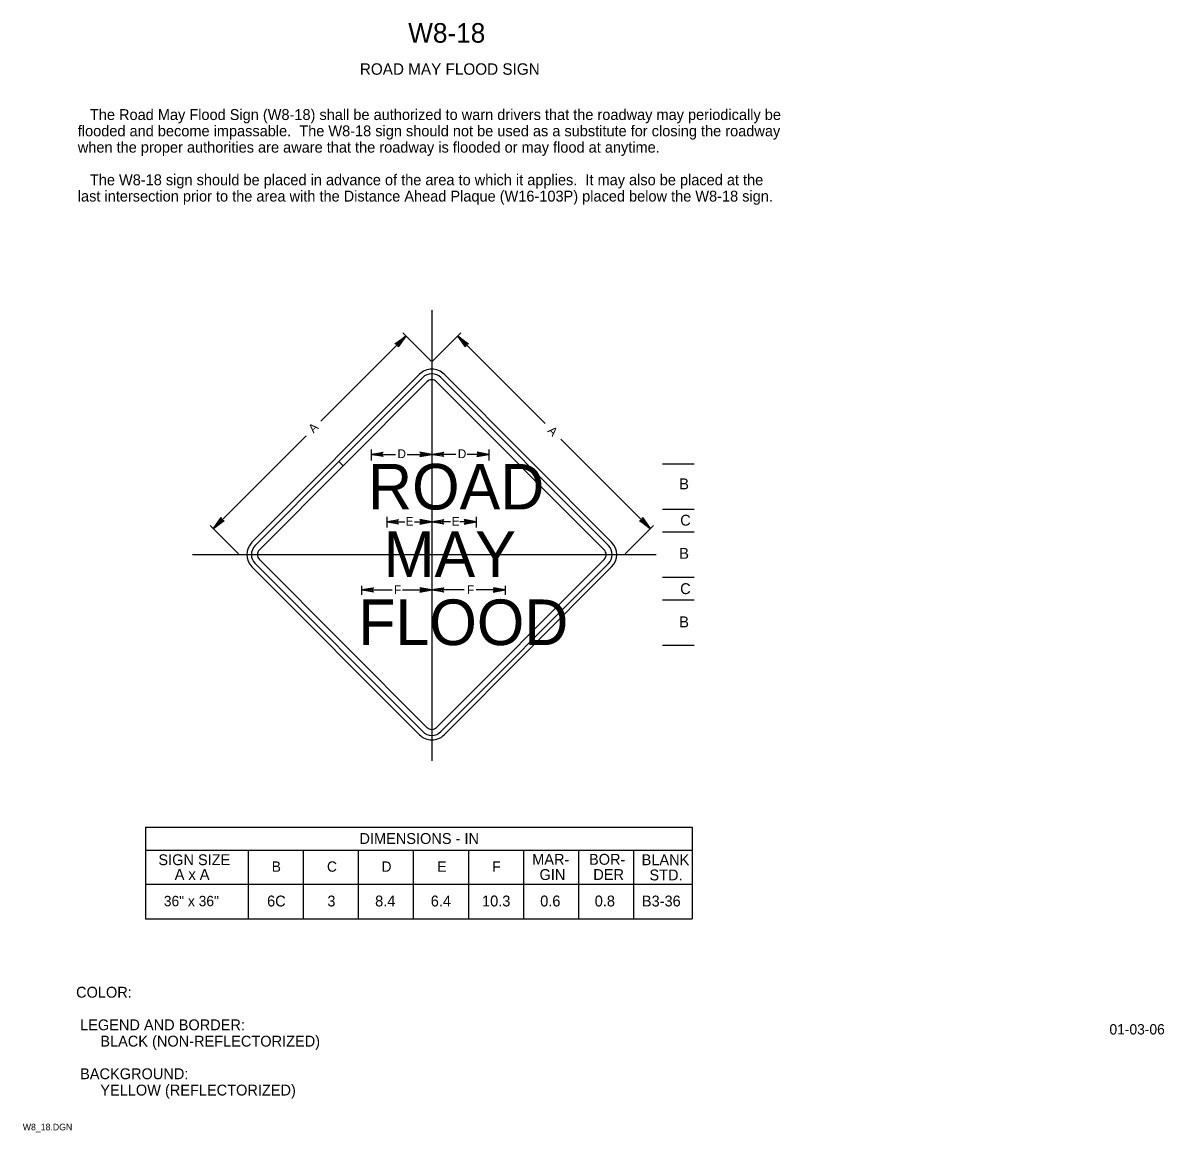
# Model space of a CAD drawing. Extents: x 0.013 to 0.275, y 0.004 to 0.259.
import ezdxf

# ---------------------------------------------------------------- set-up
doc = ezdxf.new("R2010")
doc.units = 0
for name, color, linetype in [('1', 7, 'Continuous'), ('2', 7, 'Continuous'), ('3', 7, 'Continuous'), ('4', 7, 'Continuous')]:
    doc.layers.add(name, color=color, linetype=linetype)

# ---------------------------------------------------------------- blocks, each defined once
blk = doc.blocks.new('RARROW')
at = {"layer": '3'}
for p, q in [((-2.156, 0.28500000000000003), (-2.2665, 0.384625)), ((-2.2665, 0.384625), (0, 0)), ((0, 0), (-2.2665, -0.379125)), ((-2.156, 0.28500000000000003), (-2.075625, 0.12075)), ((0, 0), (-2.156, 0.28500000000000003)), ((-2.14975, -0.2705), (0, 0)), ((-2.075625, 0.12075), (0, 0)), ((0, 0), (-2.074, -0.108)), ((-2.2665, -0.379125), (-2.14975, -0.2705)), ((-2.074, -0.108), (-2.14975, -0.2705))]:
    blk.add_line(p, q, dxfattribs=at)

msp = doc.modelspace()

# ---------------------------------------------------------------- linework, layer by layer
at = {"layer": '2'}
for p, q in [((0.08529993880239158, 0.15817754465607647), (0.10455482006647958, 0.1774918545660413)), ((0.10553914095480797, 0.17651056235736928), (0.08628425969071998, 0.15719625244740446)), ((0.14626937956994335, 0.13788194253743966), (0.10775961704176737, 0.17651056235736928)), ((0.1087439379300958, 0.17749185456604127), (0.14725370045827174, 0.13886323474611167)), ((0.06604505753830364, 0.13886323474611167), (0.08529993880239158, 0.15817754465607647)), ((0.08529993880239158, 0.15817754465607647), (0.08628425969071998, 0.15719625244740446)), ((0.08628425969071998, 0.15719625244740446), (0.08529993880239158, 0.15817754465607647)), ((0.08628425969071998, 0.15719625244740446), (0.06702937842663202, 0.13788194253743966)), ((0.10455482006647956, 0.09605838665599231), (0.06604505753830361, 0.13468700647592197)), ((0.06702937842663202, 0.13566829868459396), (0.10553914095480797, 0.0970396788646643)), ((0.10775961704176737, 0.0970396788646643), (0.14626937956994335, 0.13566829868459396)), ((0.14725370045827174, 0.13468700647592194), (0.10874393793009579, 0.09605838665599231))]:
    msp.add_line(p, q, dxfattribs=at)
for centre, radius, start, end in [((0.10664937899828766, 0.17540374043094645), 0.004, 44.91171689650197, 135.0882831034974), ((0.10664937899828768, 0.17540374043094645), 0.0029576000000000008, 44.9117168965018, 135.08828310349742), ((0.10664937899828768, 0.17540374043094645), 0.0015676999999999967, 44.91171689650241, 135.08828310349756), ((0.0681396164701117, 0.1367751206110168), 0.004, 135.0882831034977, 224.9117168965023), ((0.14515914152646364, 0.1367751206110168), 0.004, 315.08828310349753, 44.9117168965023), ((0.06813961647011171, 0.1367751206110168), 0.002957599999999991, 135.08828310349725, 224.911716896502), ((0.06813961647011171, 0.1367751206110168), 0.0015676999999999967, 135.0882831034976, 224.91171689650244), ((0.14515914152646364, 0.1367751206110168), 0.001567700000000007, 315.08828310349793, 44.91171689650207), ((0.14515914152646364, 0.1367751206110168), 0.0029576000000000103, 315.0882831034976, 44.911716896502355), ((0.10664937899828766, 0.09814650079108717), 0.004, 224.9117168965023, 315.0882831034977), ((0.10664937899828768, 0.09814650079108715), 0.0029576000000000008, 224.91171689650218, 315.0882831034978), ((0.10664937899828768, 0.09814650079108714), 0.0015676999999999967, 224.91171689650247, 315.0882831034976)]:
    msp.add_arc(centre, radius, start, end, dxfattribs=at)
at = {"layer": '3'}
for p, q in [((0.10664937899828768, 0.19299702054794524), (0.10664937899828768, 0.08936186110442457)), ((0.081150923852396, 0.16748690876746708), (0.10069136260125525, 0.1870273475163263)), ((0.10649052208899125, 0.1812281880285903), (0.09997541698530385, 0.1877432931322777)), ((0.1068082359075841, 0.1812281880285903), (0.11332334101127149, 0.1877432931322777)), ((0.13273648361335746, 0.16689825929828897), (0.1126073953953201, 0.1870273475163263)), ((0.1038165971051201, 0.17822780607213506), (0.06530683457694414, 0.13959918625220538)), ((0.14799192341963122, 0.13959918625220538), (0.10948216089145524, 0.17822780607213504)), ((0.07776676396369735, 0.1641027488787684), (0.05643338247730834, 0.14276936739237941)), ((0.1363140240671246, 0.16332071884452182), (0.156865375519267, 0.14276936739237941)), ((0.09272119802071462, 0.16097397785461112), (0.09272119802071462, 0.1584479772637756)), ((0.11977398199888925, 0.16097397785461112), (0.11977398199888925, 0.1584479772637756)), ((0.09272119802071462, 0.1598293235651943), (0.09831156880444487, 0.1598293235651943)), ((0.10096267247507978, 0.1598293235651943), (0.10664937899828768, 0.1598293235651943)), ((0.11216646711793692, 0.1598293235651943), (0.10664937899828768, 0.1598293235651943)), ((0.11977398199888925, 0.1598293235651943), (0.11477146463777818, 0.1598293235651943)), ((0.15969779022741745, 0.1576234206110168), (0.16699357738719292, 0.1576234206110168)), ((0.15969779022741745, 0.1471993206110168), (0.16699357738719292, 0.1471993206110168)), ((0.09627713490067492, 0.1454390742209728), (0.09627713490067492, 0.14297622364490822)), ((0.11682895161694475, 0.1454390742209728), (0.11682895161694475, 0.14297622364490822)), ((0.06223254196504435, 0.13697020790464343), (0.05571743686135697, 0.14348531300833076)), ((0.09627713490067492, 0.14428800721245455), (0.10044974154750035, 0.14428800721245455)), ((0.10265131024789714, 0.14428800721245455), (0.10664937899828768, 0.14428800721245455)), ((0.1109561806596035, 0.14428800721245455), (0.10664937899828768, 0.14428800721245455)), ((0.11682895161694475, 0.14428800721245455), (0.11306553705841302, 0.14428800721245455)), ((0.15106621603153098, 0.13697020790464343), (0.1575813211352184, 0.14348531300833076)), ((0.15969779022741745, 0.1419872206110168), (0.16699357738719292, 0.1419872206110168)), ((0.051641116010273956, 0.1367751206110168), (0.15819380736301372, 0.1367751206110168)), ((0.10381659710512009, 0.09532243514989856), (0.06530683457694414, 0.13395105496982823)), ((0.14799192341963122, 0.1339510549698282), (0.10948216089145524, 0.09532243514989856)), ((0.15969779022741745, 0.13156302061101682), (0.16699357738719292, 0.13156302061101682)), ((0.0904965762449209, 0.1295884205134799), (0.0904965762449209, 0.12750447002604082)), ((0.0904965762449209, 0.12864506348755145), (0.09755658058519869, 0.12864506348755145)), ((0.09988494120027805, 0.12864506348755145), (0.10664937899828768, 0.12864506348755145)), ((0.11407190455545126, 0.12864506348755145), (0.10664937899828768, 0.12864506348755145)), ((0.1235316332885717, 0.12864506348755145), (0.11685200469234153, 0.12864506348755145)), ((0.1235316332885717, 0.1295884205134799), (0.1235316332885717, 0.12750447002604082)), ((0.15969779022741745, 0.12635092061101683), (0.16699357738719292, 0.12635092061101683)), ((0.15969779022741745, 0.11592682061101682), (0.16699357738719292, 0.11592682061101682)), ((0.04080024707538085, 0.07410006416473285), (0.16650904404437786, 0.07410006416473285)), ((0.04080024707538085, 0.07410006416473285), (0.04080024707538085, 0.05297506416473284)), ((0.1665090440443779, 0.07410006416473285), (0.1665090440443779, 0.05297506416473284)), ((0.1665090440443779, 0.06872506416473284), (0.04080024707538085, 0.06872506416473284)), ((0.0644668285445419, 0.0687221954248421), (0.0644668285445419, 0.0529721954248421)), ((0.08975845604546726, 0.0687221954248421), (0.08975845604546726, 0.0529721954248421)), ((0.11505008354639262, 0.0687221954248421), (0.11505008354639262, 0.0529721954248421)), ((0.14034171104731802, 0.0687221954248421), (0.14034171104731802, 0.0529721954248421)), ((0.04080024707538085, 0.06097506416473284), (0.1665090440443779, 0.06097506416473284)), ((0.04080024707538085, 0.05297506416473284), (0.16650904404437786, 0.05297506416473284))]:
    msp.add_line(p, q, dxfattribs=at)
for points in [[(0.07711264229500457, 0.06872506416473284), (0.07711264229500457, 0.05297506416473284)], [(0.10240426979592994, 0.06872506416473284), (0.10240426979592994, 0.05297506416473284)], [(0.12769589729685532, 0.06872506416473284), (0.12769589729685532, 0.05297506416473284)], [(0.15298752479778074, 0.06872506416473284), (0.15298752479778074, 0.05297506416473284)]]:
    msp.add_lwpolyline(points, dxfattribs=at)

# ---------------------------------------------------------------- block references
for p, xscale, yscale, rotation in [((0.10069136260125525, 0.1870273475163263), 0.001340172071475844, 0.0013256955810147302, 45), ((0.1126073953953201, 0.1870273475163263), 0.001340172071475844, 0.0013256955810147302, 135), ((0.0927211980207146, 0.1598293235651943), 0.001206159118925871, 0.0013256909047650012, -179.65086766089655), ((0.10664937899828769, 0.1598293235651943), 0.001206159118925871, -0.0013256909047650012, -0.34913233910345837), ((0.10664937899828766, 0.1598293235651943), 0.001206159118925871, 0.0013256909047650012, -179.65086766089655), ((0.11977398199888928, 0.1598293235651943), 0.001206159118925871, -0.0013256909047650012, -0.34913233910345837), ((0.05643338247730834, 0.14276936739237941), 0.0013401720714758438, 0.00132569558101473, -135), ((0.09627713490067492, 0.14428800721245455), 0.001206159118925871, 0.0013256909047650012, -179.65086766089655), ((0.10664937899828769, 0.14428800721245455), 0.001206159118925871, -0.0013256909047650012, -0.34913233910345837), ((0.10664937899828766, 0.14428800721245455), 0.001206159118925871, 0.0013256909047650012, -179.65086766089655), ((0.11682895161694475, 0.14428800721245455), 0.001206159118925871, -0.0013256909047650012, -0.34913233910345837), ((0.156865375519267, 0.14276936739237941), 0.0013401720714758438, 0.0013256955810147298, -45), ((0.0904965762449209, 0.12864506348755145), 0.001206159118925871, 0.0013256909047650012, -179.65086766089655), ((0.10664937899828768, 0.12864506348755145), 0.001206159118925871, -0.0013256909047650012, -0.34913233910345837), ((0.10664937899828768, 0.12864506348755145), 0.001206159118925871, 0.0013256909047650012, -179.65086766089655), ((0.1235316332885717, 0.12864506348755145), 0.001206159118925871, -0.0013256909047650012, -0.34913233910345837)]:
    msp.add_blockref('RARROW', p, dxfattribs=dict(at, xscale=xscale, yscale=yscale, rotation=rotation))

# ---------------------------------------------------------------- texts
at = {"layer": '1'}
for s, height, p in [('W8-18', 0.0045000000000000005, (0.10122363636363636, 0.2545)), ('ROAD MAY FLOOD SIGN', 0.002625, (0.09010710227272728, 0.247125)), ('COLOR:', 0.0024997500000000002, (0.024875, 0.034874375)), (' LEGEND AND BORDER:', 0.0024997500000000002, (0.024875, 0.027374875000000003)), ('      BLACK (NON-REFLECTORIZED)', 0.0024997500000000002, (0.024875, 0.023625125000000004)), (' BACKGROUND:', 0.0024997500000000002, (0.024875, 0.016125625)), ('      YELLOW (REFLECTORIZED)', 0.0024997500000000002, (0.024875, 0.012375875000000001)), ('W8_18.DGN', 0.0015, (0.012625, 0.004375))]:
    msp.add_text(s, height=height, dxfattribs=at).set_placement(p)
at = {"layer": '2'}
for s, height, p in [('   The Road May Flood Sign (W8-18) shall be authorized to warn drivers that the roadway may periodically be', 0.0024997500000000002, (0.025270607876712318, 0.2367128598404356)), ('flooded and become impassable.  The W8-18 sign should not be used as a substitute for closing the roadway', 0.0024997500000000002, (0.025270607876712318, 0.2329631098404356)), ('when the proper authorities are aware that the roadway is flooded or may flood at anytime.', 0.0024997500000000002, (0.025270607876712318, 0.22921335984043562)), ('   The W8-18 sign should be placed in advance of the area to which it applies.  It may also be placed at the ', 0.0024997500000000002, (0.025270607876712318, 0.2217138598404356)), ('last intersection prior to the area with the Distance Ahead Plaque (W16-103P) placed below the W8-18 sign.', 0.0024997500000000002, (0.025270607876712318, 0.21796410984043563)), ('D', 0.002025, (0.09875842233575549, 0.15895107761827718)), ('D', 0.002025, (0.11262443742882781, 0.15895107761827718)), ('ROAD', 0.010489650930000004, (0.09199303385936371, 0.1471432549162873)), ('B', 0.0025, (0.16354127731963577, 0.15178895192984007)), ('E', 0.002025, (0.10065246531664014, 0.14341617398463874)), ('E', 0.002025, (0.1112356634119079, 0.14341617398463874)), ('C', 0.0025, (0.16375326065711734, 0.14343075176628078)), ('MAY', 0.010489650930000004, (0.09558942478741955, 0.13160193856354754)), ('B', 0.0025, (0.16354127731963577, 0.13579935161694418)), ('F', 0.002025, (0.09797708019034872, 0.12769182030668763)), ('F', 0.002025, (0.11473499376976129, 0.12769182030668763)), ('C', 0.0025, (0.16375326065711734, 0.1276834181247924)), ('B', 0.0025, (0.16354127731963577, 0.12005201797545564))]:
    msp.add_text(s, height=height, dxfattribs=at).set_placement(p)
msp.add_text('FLOOD', height=0.010489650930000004, rotation=360, dxfattribs=at).set_placement((0.08973138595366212, 0.11595899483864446))
at = {"layer": '3'}
for s, height, rotation, p in [('A', 0.002025, 44.99999999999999, (0.07947699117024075, 0.1645744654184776)), ('A', 0.002025, 315, (0.13311334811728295, 0.16508950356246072)), ('BLANK', 0.0024997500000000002, 360, (0.15488450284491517, 0.0653461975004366)), ('STD.', 0.0024997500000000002, 360, (0.15668432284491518, 0.06184644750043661)), ('3', 0.0025, 360, (0.08264614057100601, 0.055853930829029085)), ('6.4', 0.0025, 360, (0.1064120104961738, 0.055853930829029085)), ('0.6', 0.0025, 360, (0.13157445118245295, 0.055853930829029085)), ('B3-36', 0.0025, 360, (0.1549483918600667, 0.05585006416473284))]:
    msp.add_text(s, height=height, rotation=rotation, dxfattribs=at).set_placement(p)
for s, height, p in [('DIMENSIONS - IN', 0.0024997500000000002, (0.09001775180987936, 0.07022506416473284)), ('SIGN SIZE', 0.0024997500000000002, (0.043800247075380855, 0.06535006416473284)), ('B', 0.0023752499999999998, (0.06985051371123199, 0.06383846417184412)), ('C', 0.0023752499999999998, (0.08255230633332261, 0.06383846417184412)), ('D', 0.0023752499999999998, (0.0950971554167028, 0.06383846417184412)), ('E', 0.0023752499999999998, (0.10790295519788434, 0.06383846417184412)), ('F', 0.0023752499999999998, (0.12054641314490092, 0.06383846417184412)), ('MAR-', 0.0024997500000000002, (0.12972368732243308, 0.06543899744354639)), ('BOR-', 0.0024997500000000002, (0.14279002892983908, 0.06544286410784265)), ('A x A', 0.0024997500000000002, (0.04755024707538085, 0.06197506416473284)), ('GIN', 0.0024997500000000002, (0.1314110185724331, 0.061939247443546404)), ('DER', 0.0024997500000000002, (0.14377477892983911, 0.061943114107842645)), ('36" x 36"', 0.0023752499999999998, (0.04504565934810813, 0.05591243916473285)), ('6C', 0.0025, (0.06878596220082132, 0.055853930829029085)), ('8.4', 0.0025, (0.09362228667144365, 0.055853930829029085)), ('10.3', 0.0025, (0.11820482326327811, 0.055853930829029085)), ('0.8', 0.0025, (0.14410813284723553, 0.055853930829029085))]:
    msp.add_text(s, height=height, dxfattribs=at).set_placement(p)
at = {"layer": '4'}
msp.add_text('01-03-06', height=0.0023752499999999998, dxfattribs=at).set_placement((0.2624358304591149, 0.026409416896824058))

doc.saveas('drawing.dxf')
